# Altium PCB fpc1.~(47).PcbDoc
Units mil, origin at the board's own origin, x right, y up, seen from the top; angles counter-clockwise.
Board outline 3523.62 x 288.66 mil, 2 copper layers (Top Layer, Bottom Layer), stack 1.929 mil thick; 5 components, 5 nets, 20 pads, 5 vias.
Unrouted connection lines stored in the file: 4.
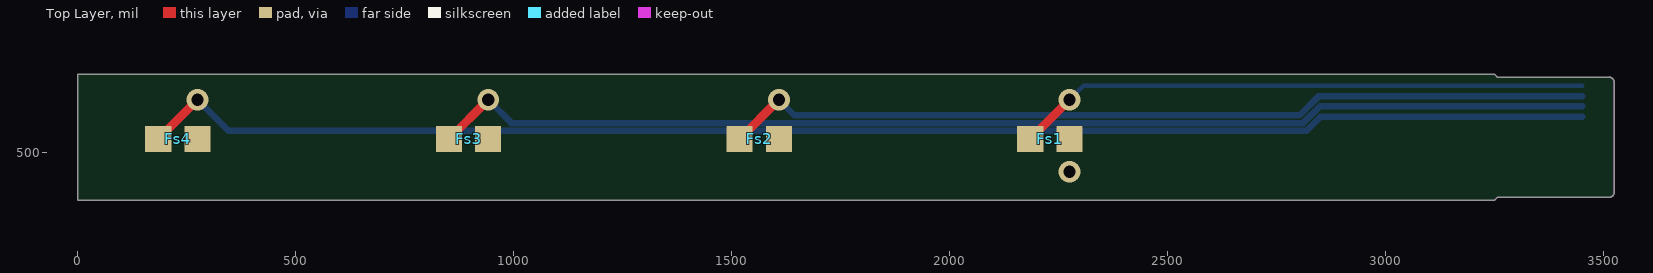
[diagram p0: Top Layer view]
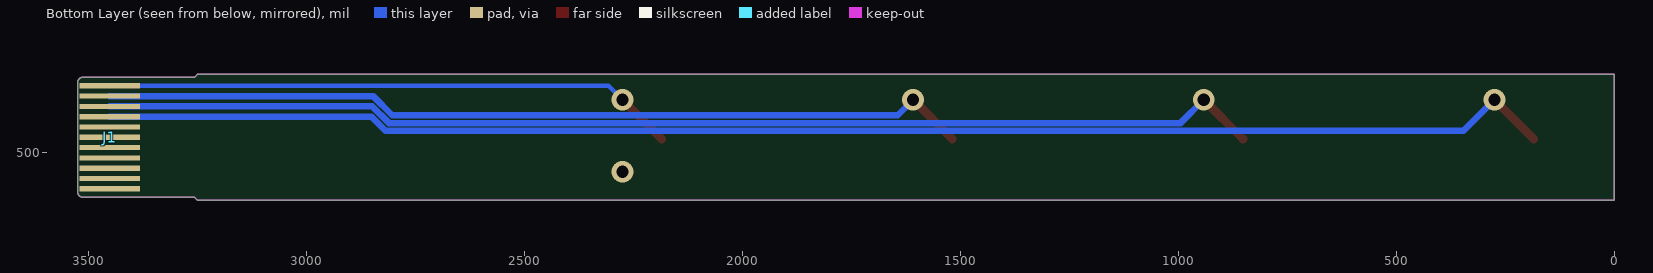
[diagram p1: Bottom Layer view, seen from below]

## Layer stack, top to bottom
Top Solder: solder mask 0.4, Solder Resist, Dk 3.5
Top Layer: signal copper 0.4724
Dielectric 1: dielectric 0.9843, FR-4, Dk 4.8
Bottom Layer: signal copper 0.4724
Bottom Solder: solder mask 0.4, Solder Resist, Dk 3.5

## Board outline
0.5,389.5 0.5,678.16 3249.87,678.16 3256.41,671.63 3512.31,671.63 cw(c3512.31,659.82) 3524.12,659.82 3524.12,407.85 cw(c3512.31,407.85) 3512.31,396.04 3256.41,396.04 3249.87,389.5

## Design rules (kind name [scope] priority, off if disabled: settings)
BoardOutlineClearance [All] p1: gap=0 ignorepadtopadclearanceinfootprint=FALSE except(10: Via-OutlineEdge Via-CavityEdge Via-CutoutEdge Via-SplitBarrior Fill-OutlineEdge Fill-CavityEdge Fill-CutoutEdge Fill-SplitBarrior Poly-OutlineEdge Poly-CavityEdge Poly-CutoutEdge Poly-SplitBarrior Region-OutlineEdge Region-CavityEdge Region-CutoutEdge Region-SplitBarrior Text-OutlineEdge Text-CavityEdge Text-CutoutEdge Text-SplitBarrior)
Clearance [All] p1: gap=3 ignorepadtopadclearanceinfootprint=TRUE except(0: Arc-Hole Track-Hole SMDPad-Hole THPad-Hole Via-Hole Fill-Hole Poly-Hole Region-Hole Text-Hole)
DiffPairsRouting [All] p1: maxlimit=10 minlimit=10 mostfreqgap=10 toplayer_minwidth=15 toplayer_maxwidth=15 toplayer_prefwidth=15 bottomlayer_minwidth=15 bottomlayer_maxwidth=15 bottomlayer_prefwidth=15 substack1={6BAC4FC8-8DE6-4E41-AF8A-9441F3E19743} toplayer_{6bac4fc8-8de6-4e41-af8a-9441f3e19743}_minwidth=15 toplayer_{6bac4fc8-8de6-4e41-af8a-9441f3e19743}_maxwidth=15 toplayer_{6bac4fc8-8de6-4e41-af8a-9441f3e19743}_prefwidth=15 bottomlayer_{6bac4fc8-8de6-4e41-af8a-9441f3e19743}_minwidth=15 bottomlayer_{6bac4fc8-8de6-4e41-af8a-9441f3e19743}_maxwidth=15 bottomlayer_{6bac4fc8-8de6-4e41-af8a-9441f3e19743}_prefwidth=15 maxuncoupledlength=500
MinimumSolderMaskSliver [All] p1: minsoldermaskwidth=1.97
PolygonConnect [All] p1: connectstyle=Relief reliefconductorwidth=10 reliefentries=4 polygonreliefangle="90 Angle" airgapwidth=10
RoutingVias [All] p1: holewidth=28 width=50 viastyle="Through Hole" minholewidth=28 minwidth=50 maxholewidth=28 maxwidth=50
SilkToSilkClearance [All] p1: silktosilkclearance=1.97
SilkToSolderMaskClearance [IsPad] p1: minsilkscreentomaskgap=1.97 clearancetoexposedcopper=TRUE
SolderMaskExpansion [All] p1: expansion=4 istentingtop=FALSE
Width [All] p1: maxlimit=20 minlimit=5 preferedwidth=15 substack1={6BAC4FC8-8DE6-4E41-AF8A-9441F3E19743} toplayer_{6bac4fc8-8de6-4e41-af8a-9441f3e19743}_minwidth=10 toplayer_{6bac4fc8-8de6-4e41-af8a-9441f3e19743}_maxwidth=10 toplayer_{6bac4fc8-8de6-4e41-af8a-9441f3e19743}_prefwidth=10 bottomlayer_{6bac4fc8-8de6-4e41-af8a-9441f3e19743}_minwidth=10 bottomlayer_{6bac4fc8-8de6-4e41-af8a-9441f3e19743}_maxwidth=10 bottomlayer_{6bac4fc8-8de6-4e41-af8a-9441f3e19743}_prefwidth=10 minimp=50.000000 maximp=50.000000 favimp=50.000000
26 further rules are at their usual default settings.

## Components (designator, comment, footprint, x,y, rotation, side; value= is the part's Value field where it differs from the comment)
Fs1 "ForceSensor" sensor_connector 2230,530 r0 top
Fs2 "ForceSensor" sensor_connector 1563.33,530 r0 top
Fs3 "ForceSensor" sensor_connector 896.67,530 r0 top
Fs4 "ForceSensor" sensor_connector 230,530 r0 top
J1 "FPC_connector" FPC_connector 3450.79,533.82 r180 bottom

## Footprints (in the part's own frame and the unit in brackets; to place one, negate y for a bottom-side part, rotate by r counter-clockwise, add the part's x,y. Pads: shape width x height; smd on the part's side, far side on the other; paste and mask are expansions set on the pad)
FPC_connector [mm]
  rect 3.5x0.3 smd: 0(0,3) 1(0,3) 2(0,2.4) 3(0,1.8) 4(0,1.2) 5(0,0.6) 6(0,0) 7(0,-0.6) 8(0,-1.2) 9(0,-1.8) 10(0,-2.4) 11(0,-3)
sensor_connector [mil]
  rect 60x60 smd: 0(-45,0) 1(45,0)

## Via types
v1: diameter 50, hole 28, Top Layer to Bottom Layer, 5 vias

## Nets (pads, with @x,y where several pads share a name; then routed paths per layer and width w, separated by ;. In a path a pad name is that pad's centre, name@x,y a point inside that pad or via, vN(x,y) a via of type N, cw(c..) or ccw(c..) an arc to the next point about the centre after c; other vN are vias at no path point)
FS1: Fs1.0 J1.1 | length 1316.3
  Top Layer w20: Fs1.0 v1(2275,620)
  Bottom Layer w10: v1(2275,620) 2306.93,651.93 J1.1
FS2: Fs2.0 J1.2 | length 2002.6
  Top Layer w20: Fs2.0 v1(1608.33,620)
  Bottom Layer w15: v1(1608.33,620) 1643.83,584.5 2802.94,584.5 2846.75,628.31 J1.2
FS3: Fs3.0 J1.3 | length 2674.4
  Top Layer w20: Fs3.0 v1(941.67,620)
  Bottom Layer w15: v1(941.67,620) 995.17,566.5 2810.39,566.5 2848.58,604.68 J1.3
FS4: Fs4.0 J1.4 | length 3346.2
  Top Layer w20: Fs4.0 v1(275,620)
  Bottom Layer w15: v1(275,620) 346.5,548.5 2817.85,548.5 2850.41,581.06 J1.4
GND: Fs1.1 Fs2.1 Fs3.1 Fs4.1 J1.0
pads on no net: J1.5 J1.6 J1.7 J1.8 J1.9 J1.10 J1.11
copper on no net:
  other v1: 2275,455

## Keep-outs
Keep-Out Layer:
  the board outline again, w0.5

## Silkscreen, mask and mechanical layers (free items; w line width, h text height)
Board Shape:
  the board outline again, w0.5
